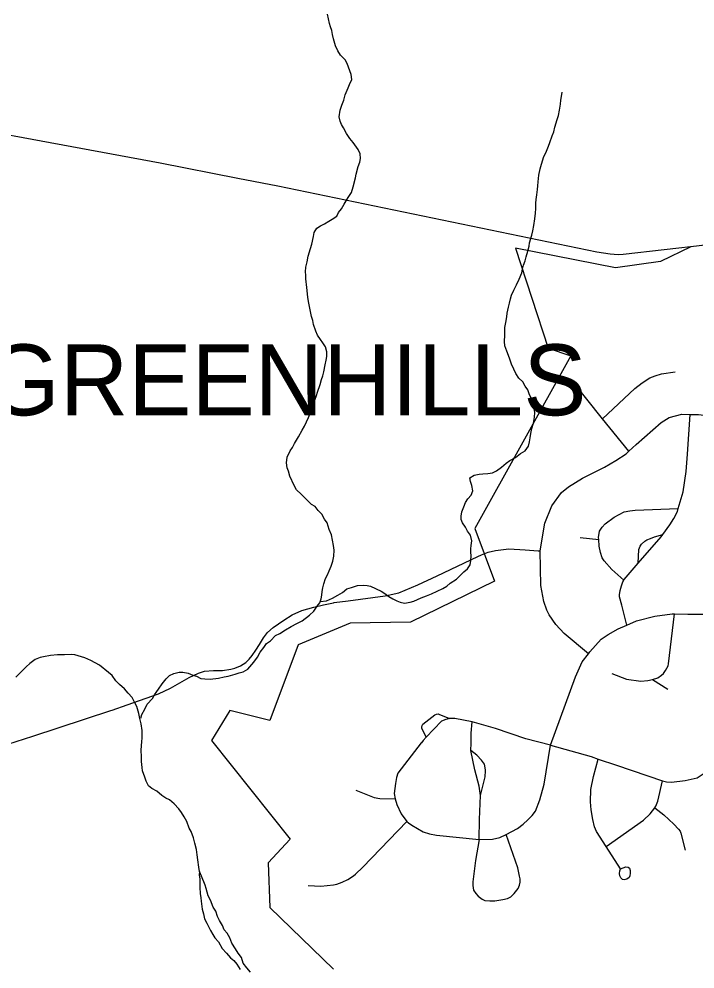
# Model space of a CAD drawing. Extents: x 0 to 69.5, y -4.5 to 22.
# Drawn here: x 6.973 to 7.876, y 18.138 to 19.407 of the extents above; entities that cross this region are included whole.
import ezdxf

# ---------------------------------------------------------------- set-up
doc = ezdxf.new("R2010")
doc.units = 0
for name, color, linetype in [('GM_X_City_Street', 7, 'Continuous'), ('GM_X_Corporation', 7, 'Continuous'), ('GM_X_Corporation_Text', 7, 'Continuous'), ('GM_X_County_Road', 7, 'Continuous'), ('GM_X_Major_Lake', 7, 'Continuous'), ('GM_X_Minor_River', 7, 'Continuous')]:
    doc.layers.add(name, color=color, linetype=linetype)

msp = doc.modelspace()

# ---------------------------------------------------------------- linework, layer by layer
at = {"layer": 'GM_X_City_Street'}
for points in [[(6.7657, 19.288), (7.1613, 19.2149), (7.265, 19.1946), (7.3185, 19.1843), (7.7448, 19.0962), (7.7625, 19.0934), (7.7731, 19.0923), (7.7798, 19.0928), (7.9442, 19.1116)], [(7.7524, 18.8732), (7.7958, 18.9137), (7.8055, 18.9212), (7.8155, 18.9276), (7.8229, 18.9305), (7.8313, 18.9332), (7.8496, 18.9357)], [(7.7875, 18.8296), (7.7524, 18.8732), (7.7122, 18.9231)], [(7.6692, 18.6966), (7.6752, 18.7335), (7.6847, 18.7567), (7.6977, 18.7746), (7.707, 18.7823), (7.7256, 18.7939), (7.7549, 18.8086), (7.7703, 18.8172), (7.7838, 18.8263), (7.7875, 18.8296), (7.7975, 18.8388), (7.8306, 18.8682), (7.8414, 18.8747), (7.8582, 18.8791), (7.8695, 18.8787), (7.8807, 18.8787), (7.8947, 18.8772), (7.9195, 18.8749)], [(7.7847, 18.5973), (7.7781, 18.6241), (7.7753, 18.6352), (7.7753, 18.638), (7.776, 18.6437), (7.7778, 18.65), (7.7796, 18.6551), (7.7808, 18.6574), (7.7815, 18.6586), (7.8001, 18.6801), (7.8306, 18.7153), (7.8331, 18.7186), (7.8425, 18.7313), (7.8476, 18.7397), (7.8525, 18.7492), (7.8537, 18.7531), (7.8602, 18.7753), (7.8644, 18.8025), (7.8659, 18.826), (7.8695, 18.8787)], [(7.7808, 18.6574), (7.7648, 18.6717), (7.7548, 18.6832), (7.752, 18.6873), (7.7498, 18.6944), (7.7479, 18.703), (7.7473, 18.7118), (7.7471, 18.7144), (7.7485, 18.7231), (7.7519, 18.7284), (7.756, 18.7328), (7.7681, 18.7415), (7.7812, 18.7487), (7.7889, 18.7502), (7.796, 18.751), (7.8537, 18.7531)], [(7.8001, 18.6801), (7.8008, 18.6985), (7.8025, 18.7031), (7.8045, 18.7058), (7.809, 18.7096), (7.8118, 18.7112), (7.8167, 18.7132), (7.8219, 18.7152), (7.8331, 18.7186)], [(7.7225, 18.7144), (7.7473, 18.7118)], [(7.5998, 18.6951), (7.6096, 18.6973), (7.6272, 18.6994), (7.6491, 18.698), (7.6662, 18.6968), (7.6692, 18.6966), (7.6692, 18.6966)], [(7.7335, 18.5592), (7.7011, 18.5865), (7.6899, 18.5984), (7.6813, 18.611), (7.6778, 18.6173), (7.6739, 18.6291), (7.67, 18.6502), (7.6692, 18.6966)], [(7.683, 18.437), (7.7164, 18.5286), (7.725, 18.5485), (7.7335, 18.5592), (7.7356, 18.5619), (7.7505, 18.5785), (7.7599, 18.585), (7.7733, 18.5923), (7.7847, 18.5973), (7.7976, 18.603), (7.8224, 18.6094), (7.8453, 18.6126), (7.8487, 18.6125), (7.8665, 18.6123), (7.8925, 18.612)], [(7.7647, 18.5329), (7.7846, 18.5255), (7.8035, 18.5226), (7.8129, 18.5234), (7.8193, 18.5247), (7.8262, 18.5271), (7.8314, 18.5305), (7.834, 18.5327), (7.8365, 18.5368), (7.8401, 18.5432), (7.8408, 18.5458), (7.8487, 18.6125)], [(7.8193, 18.5247), (7.8395, 18.512)], [(7.5169, 18.4478), (7.5111, 18.4599), (7.511, 18.461), (7.5112, 18.4633), (7.5123, 18.4652), (7.5283, 18.4777), (7.5304, 18.4787), (7.5326, 18.4789), (7.5338, 18.4786), (7.5481, 18.4728)], [(7.683, 18.437), (7.6501, 18.4454), (7.6095, 18.4596), (7.5783, 18.4681), (7.5549, 18.4726), (7.5481, 18.4728), (7.5429, 18.4715), (7.5374, 18.469), (7.5169, 18.4478), (7.5127, 18.4435), (7.5103, 18.4403)], [(7.5876, 18.3112), (7.5879, 18.3378), (7.5893, 18.3697), (7.5874, 18.3823), (7.582, 18.4041), (7.5764, 18.4301), (7.5767, 18.4396), (7.5771, 18.4533), (7.5783, 18.4681)], [(7.5103, 18.4403), (7.5102, 18.4403), (7.4791, 18.3996), (7.4773, 18.3938), (7.4756, 18.386), (7.4739, 18.3724), (7.4753, 18.3653), (7.4774, 18.3578), (7.4835, 18.3455), (7.4908, 18.3354), (7.4932, 18.3333), (7.4978, 18.3302), (7.5127, 18.3214), (7.521, 18.3188), (7.5304, 18.3171), (7.5876, 18.3112), (7.6053, 18.3114), (7.6153, 18.3137), (7.6237, 18.3177), (7.6388, 18.326), (7.6464, 18.3318), (7.6524, 18.3373), (7.6584, 18.3434), (7.6627, 18.3492), (7.6688, 18.3642), (7.6744, 18.385), (7.683, 18.437)], [(7.683, 18.437), (7.7372, 18.4219), (7.7464, 18.4185), (7.7712, 18.4106), (7.8324, 18.3894), (7.8378, 18.3882), (7.8444, 18.3878), (7.8627, 18.3899), (7.8788, 18.3936), (7.9083, 18.4129)], [(7.5893, 18.3697), (7.5955, 18.3947), (7.5959, 18.403), (7.5959, 18.4043), (7.5945, 18.4118), (7.5908, 18.417), (7.5844, 18.4237), (7.5764, 18.4301)], [(7.7764, 18.272), (7.7798, 18.2735), (7.7835, 18.2745), (7.7867, 18.2742), (7.7886, 18.2727), (7.7894, 18.2699), (7.7895, 18.2661), (7.7889, 18.2627), (7.788, 18.2604), (7.7848, 18.2581), (7.7812, 18.2573), (7.7791, 18.2579), (7.7768, 18.2598), (7.7756, 18.2624), (7.775, 18.2659), (7.7755, 18.2693), (7.7764, 18.272), (7.7575, 18.3017), (7.7445, 18.322), (7.7417, 18.3281), (7.7393, 18.3378), (7.7371, 18.3508), (7.7363, 18.3614), (7.7368, 18.3781), (7.7403, 18.3951), (7.7464, 18.4185)], [(7.7575, 18.3017), (7.8072, 18.3368), (7.816, 18.3455), (7.8193, 18.3493), (7.8223, 18.3536), (7.8237, 18.3557), (7.8263, 18.3623), (7.8324, 18.3894)], [(7.4228, 18.3771), (7.4474, 18.3672), (7.455, 18.3658), (7.4753, 18.3653)], [(7.8223, 18.3536), (7.8344, 18.344), (7.8476, 18.3318), (7.854, 18.325), (7.8561, 18.3221), (7.8571, 18.3197), (7.8629, 18.2971)], [(7.3591, 18.2496), (7.3762, 18.2487), (7.3929, 18.2505), (7.3972, 18.2513), (7.4046, 18.2541), (7.4122, 18.2576), (7.4198, 18.2626), (7.4223, 18.2647), (7.432, 18.274), (7.4908, 18.3354)], [(7.5876, 18.3112), (7.5826, 18.2829), (7.5791, 18.2545), (7.5792, 18.2495), (7.5802, 18.2435), (7.5831, 18.2388), (7.5864, 18.2353), (7.5917, 18.2316), (7.595, 18.2297), (7.6017, 18.229), (7.6083, 18.2293), (7.6193, 18.2309), (7.6254, 18.2325), (7.63, 18.2344), (7.6344, 18.2388), (7.6395, 18.2458), (7.6415, 18.25), (7.6423, 18.2542), (7.6423, 18.2588), (7.6415, 18.2621), (7.6392, 18.2732), (7.6237, 18.3177)]]:
    msp.add_lwpolyline(points, dxfattribs=at)
at = {"layer": 'GM_X_Corporation'}
msp.add_lwpolyline([(8.8, 18.7458), (8.6784, 18.7536), (8.6177, 19.0337), (8.625, 19.1774), (7.9442, 19.1116), (7.8706, 19.1028), (7.8298, 19.0832), (7.7697, 19.0749), (7.636, 19.1009), (7.6799, 18.9673), (7.7101, 18.9572), (7.5816, 18.7265), (7.6081, 18.656), (7.4956, 18.6014), (7.4151, 18.6003), (7.3459, 18.5712), (7.308, 18.47), (7.2545, 18.4833), (7.2297, 18.4434), (7.3351, 18.3114), (7.3057, 18.2799), (7.3077, 18.2201), (7.3929, 18.1381)], dxfattribs=at)
at = {"layer": 'GM_X_County_Road'}
for points in [[(7.3929, 18.6274), (7.3936, 18.6275), (7.4126, 18.6301), (7.4621, 18.6368), (7.4803, 18.6408), (7.5055, 18.6511), (7.5313, 18.6634), (7.5857, 18.689), (7.5907, 18.6914), (7.5997, 18.6951), (7.5998, 18.6951)], [(7.0971, 18.484), (7.1173, 18.491), (7.1589, 18.5057), (7.1751, 18.5134), (7.1877, 18.5204), (7.1999, 18.5276), (7.2127, 18.5333), (7.2205, 18.5358), (7.2325, 18.5368), (7.2444, 18.537), (7.2558, 18.5386), (7.2611, 18.5399), (7.2687, 18.5433), (7.2756, 18.5477), (7.2803, 18.552), (7.2843, 18.5571), (7.289, 18.564), (7.2938, 18.5718), (7.2995, 18.5804), (7.3049, 18.5874), (7.3123, 18.5942), (7.3264, 18.6041), (7.3375, 18.611), (7.3506, 18.6169), (7.3665, 18.6213), (7.3795, 18.6245), (7.3929, 18.6274)], [(6.6748, 18.2683), (6.7285, 18.2655), (6.8486, 18.3747), (6.8655, 18.3843), (6.8923, 18.4031), (6.9436, 18.4327), (6.9578, 18.4383), (6.9913, 18.4492), (7.0954, 18.4834), (7.0971, 18.484)]]:
    msp.add_lwpolyline(points, dxfattribs=at)
at = {"layer": 'GM_X_Major_Lake'}
msp.add_lwpolyline([(7.2819, 18.1341), (7.2771, 18.1399), (7.2723, 18.1461), (7.2698, 18.1534), (7.2657, 18.1592), (7.262, 18.1649), (7.2572, 18.1726), (7.2544, 18.1799), (7.2507, 18.1861), (7.247, 18.1907), (7.2444, 18.1961), (7.2404, 18.203), (7.2378, 18.2084), (7.2357, 18.2153), (7.232, 18.2207), (7.2284, 18.2299), (7.2255, 18.236), (7.2227, 18.2456), (7.2212, 18.2502), (7.2165, 18.2621), (7.214, 18.2686), (7.2132, 18.2641), (7.2142, 18.2583), (7.2145, 18.253), (7.2143, 18.2469), (7.2146, 18.2389), (7.2156, 18.2332), (7.2162, 18.2286), (7.2175, 18.2179), (7.2193, 18.2118), (7.2203, 18.205), (7.2236, 18.1992), (7.2284, 18.1896), (7.2317, 18.1842), (7.2342, 18.1796), (7.2391, 18.1745), (7.2442, 18.1657), (7.2498, 18.1595), (7.2553, 18.1529), (7.2598, 18.1494), (7.2639, 18.1448), (7.2683, 18.1374)], dxfattribs=at)
at = {"layer": 'GM_X_Minor_River'}
for points in [[(7.3652, 19.0042), (7.3634, 19.0099), (7.3607, 19.0229), (7.3597, 19.0298), (7.3586, 19.0355), (7.3574, 19.0485), (7.3561, 19.0599), (7.3558, 19.0649), (7.3555, 19.0694), (7.356, 19.0755), (7.3577, 19.0827), (7.359, 19.0903), (7.3622, 19.1005), (7.3639, 19.1062), (7.366, 19.1164), (7.3672, 19.1217), (7.3708, 19.1277), (7.3754, 19.1306), (7.3808, 19.1336), (7.3865, 19.1369), (7.3911, 19.1395), (7.3973, 19.1439), (7.3997, 19.1488), (7.4036, 19.1537), (7.4071, 19.1597), (7.4126, 19.1687), (7.4169, 19.1755), (7.4193, 19.183), (7.4222, 19.1951), (7.4231, 19.1997), (7.426, 19.2099), (7.428, 19.2159), (7.4288, 19.2209), (7.4286, 19.2269), (7.426, 19.2327), (7.4194, 19.242), (7.4146, 19.2474), (7.4102, 19.2539), (7.4061, 19.2616), (7.4036, 19.2662), (7.4018, 19.2708), (7.4004, 19.2762), (7.4017, 19.2853), (7.4041, 19.2921), (7.4065, 19.2985), (7.4085, 19.3057), (7.4125, 19.3151), (7.4141, 19.3197), (7.4173, 19.3264), (7.4163, 19.3329), (7.4113, 19.3475), (7.4084, 19.3525), (7.4024, 19.3587), (7.3987, 19.3645), (7.3954, 19.371), (7.393, 19.3806), (7.3916, 19.3863), (7.3905, 19.3916), (7.3891, 19.3966), (7.3877, 19.4012), (7.3849, 19.4134)], [(7.6444, 19.0682), (7.6456, 19.0727), (7.6469, 19.0784), (7.6489, 19.0841), (7.6505, 19.0894), (7.6526, 19.0969), (7.6546, 19.1034), (7.6547, 19.1079), (7.6579, 19.1181), (7.6592, 19.1242), (7.6605, 19.1314), (7.6618, 19.1401), (7.6627, 19.1477), (7.6632, 19.1538), (7.6634, 19.161), (7.6638, 19.1659), (7.6647, 19.1724), (7.6656, 19.1792), (7.6661, 19.1841), (7.6662, 19.1895), (7.6667, 19.194), (7.6675, 19.1986), (7.6692, 19.2069), (7.6709, 19.213), (7.6741, 19.2235), (7.6765, 19.2284), (7.6801, 19.2371), (7.6821, 19.242), (7.6853, 19.2511), (7.6873, 19.2564), (7.6889, 19.2624), (7.6918, 19.273), (7.6934, 19.2783), (7.6951, 19.2851), (7.6964, 19.2931), (7.6969, 19.2988), (7.6974, 19.3037), (7.6983, 19.3094)], [(7.3753, 18.6292), (7.3834, 18.63), (7.3915, 18.6336), (7.3988, 18.6373), (7.4049, 18.6409), (7.4107, 18.6458), (7.4168, 18.6479), (7.4249, 18.6504), (7.4328, 18.651), (7.4378, 18.6505), (7.4423, 18.6493), (7.4566, 18.6429), (7.4615, 18.6398), (7.4667, 18.6359), (7.4723, 18.6324), (7.4776, 18.63), (7.4821, 18.628), (7.4878, 18.6267), (7.4954, 18.6281), (7.5003, 18.6295), (7.5099, 18.6339), (7.5172, 18.6368), (7.5237, 18.6393), (7.539, 18.6466), (7.5444, 18.6495), (7.549, 18.6533), (7.5571, 18.6588), (7.5618, 18.6633), (7.5672, 18.6685), (7.5722, 18.6726), (7.5754, 18.6782), (7.5766, 18.6839), (7.5767, 18.69), (7.5765, 18.6949), (7.5765, 18.6995), (7.577, 18.704), (7.5779, 18.7101), (7.5758, 18.7174), (7.5721, 18.7228), (7.5695, 18.7282), (7.5655, 18.7339), (7.5637, 18.7385), (7.5634, 18.7431), (7.5643, 18.7488), (7.5671, 18.7556), (7.5694, 18.7612), (7.5726, 18.7661), (7.5769, 18.771), (7.5789, 18.777), (7.5779, 18.7839), (7.5761, 18.7893), (7.5751, 18.7942), (7.5808, 18.7979), (7.5877, 18.7993), (7.5926, 18.7996), (7.5991, 18.7998), (7.6052, 18.8008), (7.6109, 18.8034), (7.6175, 18.8086), (7.6237, 18.8138), (7.6287, 18.8175), (7.6363, 18.8215), (7.6429, 18.8267), (7.649, 18.8304), (7.6537, 18.8364), (7.655, 18.8421), (7.6555, 18.8478), (7.6567, 18.8534), (7.658, 18.8599), (7.66, 18.8674), (7.6613, 18.8754), (7.6619, 18.8815), (7.6612, 18.888), (7.6584, 18.896), (7.6566, 18.9017), (7.6544, 18.9064), (7.6526, 18.9117), (7.6489, 18.9167), (7.646, 18.9225), (7.6408, 18.9275), (7.6367, 18.9337), (7.6338, 18.9395), (7.6309, 18.946), (7.6284, 18.9529), (7.6266, 18.9575), (7.6244, 18.9636), (7.6219, 18.9705), (7.6216, 18.9762), (7.6218, 18.9846), (7.622, 18.9949), (7.6233, 19.0017), (7.6246, 19.0093), (7.6251, 19.0142), (7.6267, 19.0222), (7.628, 19.0275), (7.6293, 19.0335), (7.6309, 19.038), (7.634, 19.0448), (7.6376, 19.052), (7.6412, 19.0595), (7.6444, 19.0682)], [(7.1354, 18.4733), (7.1367, 18.4782), (7.141, 18.485), (7.1438, 18.4921), (7.1511, 18.4996), (7.1539, 18.5045), (7.159, 18.512), (7.1641, 18.5191), (7.1695, 18.5258), (7.1738, 18.5303), (7.1795, 18.5329), (7.1868, 18.5346), (7.1917, 18.5345), (7.1989, 18.5332), (7.2049, 18.5308), (7.2098, 18.5292), (7.2158, 18.5264), (7.2211, 18.5256), (7.228, 18.5251), (7.2394, 18.5267), (7.247, 18.5285), (7.2523, 18.5295), (7.2615, 18.532), (7.2668, 18.5338), (7.2722, 18.5352), (7.2783, 18.5385), (7.2865, 18.5482), (7.2912, 18.5546), (7.2951, 18.5614), (7.2998, 18.5674), (7.3033, 18.573), (7.3087, 18.5767), (7.3153, 18.5834), (7.3211, 18.5863), (7.3287, 18.5911), (7.3364, 18.5955), (7.3437, 18.5996), (7.351, 18.6032), (7.361, 18.6106), (7.3665, 18.6162), (7.3711, 18.6226), (7.3747, 18.6271), (7.3763, 18.6324), (7.3771, 18.6373), (7.3776, 18.6422), (7.3785, 18.6475), (7.3801, 18.6528), (7.3821, 18.6596), (7.3849, 18.6645), (7.3873, 18.6702), (7.3897, 18.6762), (7.3921, 18.683), (7.3934, 18.6895), (7.3939, 18.6974), (7.3929, 18.7036), (7.3902, 18.7181), (7.3873, 18.7253), (7.3844, 18.7341), (7.3807, 18.7388), (7.3771, 18.7457), (7.3726, 18.7504), (7.3682, 18.7558), (7.3637, 18.7585), (7.3592, 18.7632), (7.3547, 18.7675), (7.3495, 18.7725), (7.3436, 18.7783), (7.3403, 18.7841), (7.3344, 18.7964), (7.3327, 18.8029), (7.3309, 18.8075), (7.3299, 18.8144), (7.3311, 18.8216), (7.3351, 18.8302), (7.3379, 18.8347), (7.341, 18.84), (7.3434, 18.8445), (7.3461, 18.849), (7.3512, 18.858), (7.354, 18.8633), (7.3596, 18.8746), (7.3636, 18.8852), (7.3652, 18.8901), (7.3684, 18.8992), (7.3704, 18.9041), (7.3716, 18.9086), (7.3753, 18.9188), (7.3769, 18.9256), (7.3785, 18.9305), (7.3798, 18.9358), (7.3819, 18.9453), (7.3831, 18.9513), (7.384, 18.9563), (7.3841, 18.9627), (7.3824, 18.9692), (7.3787, 18.9743), (7.3757, 18.9789), (7.3717, 18.9847), (7.3691, 18.99), (7.3663, 18.9992), (7.3652, 19.0042)], [(7.214, 18.2686), (7.213, 18.2743), (7.2117, 18.2842), (7.2107, 18.2907), (7.2097, 18.298), (7.2076, 18.3064), (7.2058, 18.3133), (7.2029, 18.3217), (7.2, 18.3263), (7.1968, 18.3351), (7.1935, 18.3413), (7.1898, 18.3474), (7.1861, 18.3521), (7.1798, 18.3587), (7.1738, 18.3641), (7.1689, 18.3665), (7.1637, 18.37), (7.1566, 18.3759), (7.1502, 18.3794), (7.1457, 18.3826), (7.1424, 18.3891), (7.1407, 18.3944), (7.1378, 18.4029), (7.1371, 18.4074), (7.1365, 18.4154), (7.1363, 18.4215), (7.1361, 18.4303), (7.1362, 18.4364), (7.1367, 18.4421), (7.1372, 18.4466), (7.1372, 18.4512), (7.137, 18.4569), (7.136, 18.4657), (7.1343, 18.4729), (7.1329, 18.4794), (7.13, 18.489), (7.1271, 18.4947), (7.1238, 18.5009), (7.1183, 18.5067), (7.1134, 18.5125), (7.1071, 18.518), (7.1019, 18.523), (7.0971, 18.53), (7.0922, 18.5342), (7.0803, 18.544), (7.0687, 18.5503), (7.0608, 18.5539), (7.0472, 18.5576), (7.0422, 18.5581), (7.0335, 18.5579), (7.024, 18.5577), (7.0145, 18.5571), (7.0054, 18.555), (7.0008, 18.5543), (6.9943, 18.5514), (6.9873, 18.5462), (6.9823, 18.5418), (6.9765, 18.5358), (6.9684, 18.528)]]:
    msp.add_lwpolyline(points, dxfattribs=at)

# ---------------------------------------------------------------- texts
at = {"layer": 'GM_X_Corporation_Text'}
msp.add_text('GREENHILLS', height=0.0947, rotation=0, dxfattribs=at).set_placement((6.9287, 18.8777))

doc.saveas('drawing.dxf')
